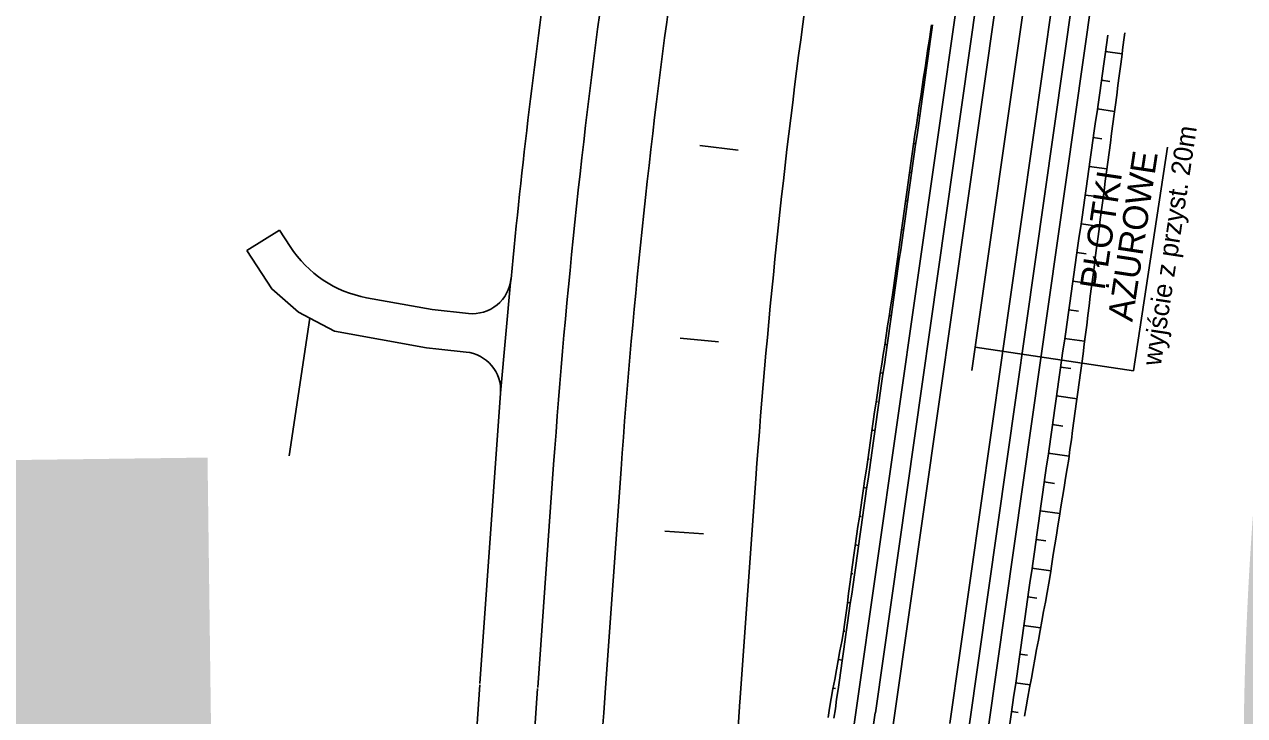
# Model space of a CAD drawing. Extents: x 6503541 to 6503743, y 5888004 to 5888145.
# Drawn here: x 6503702.276 to 6503703.793, y 5888115.915 to 5888116.773 of the extents above; entities that cross this region are included whole.
import ezdxf

# ---------------------------------------------------------------- set-up
doc = ezdxf.new("R2010")
doc.units = 0
doc.layers.add('12', color=7, linetype='Continuous')

msp = doc.modelspace()

# ---------------------------------------------------------------- linework, layer by layer
at = {"layer": '12'}
for p, q in [((6503703.334, 5888115.918), (6503705.1445, 5888128.6327)), ((6503703.3577, 5888115.9146), (6503705.1683, 5888128.6294)), ((6503703.4266, 5888115.9048), (6503705.2372, 5888128.6195)), ((6503703.4504, 5888115.9014), (6503705.2609, 5888128.6162)), ((6503703.3102, 5888115.9214), (6503703.44, 5888116.8329)), ((6503703.5216, 5888116.8185), (6503703.4539, 5888116.3433)), ((6503703.4741, 5888115.898), (6503703.6039, 5888116.8095)), ((6503703.4032, 5888116.7677), (6503703.4045, 5888116.7675)), ((6503703.6201, 5888116.7394), (6503703.6407, 5888116.7365)), ((6503703.3986, 5888116.732), (6503703.3978, 5888116.7321)), ((6503703.3923, 5888116.6965), (6503703.3944, 5888116.6962)), ((6503703.6255, 5888116.7023), (6503703.615, 5888116.7038)), ((6503703.3881, 5888116.6607), (6503703.3869, 5888116.6609)), ((6503703.61, 5888116.6681), (6503703.6313, 5888116.6651)), ((6503703.6157, 5888116.6309), (6503703.6049, 5888116.6325)), ((6503703.3815, 5888116.6253), (6503703.3842, 5888116.6249)), ((6503703.6971, 5888116.6205), (6503703.6547, 5888116.343)), ((6503703.3778, 5888116.5895), (6503703.3765, 5888116.5897)), ((6503703.5998, 5888116.5968), (6503703.6219, 5888116.5937)), ((6503703.3715, 5888116.554), (6503703.3741, 5888116.5537)), ((6503703.6059, 5888116.5596), (6503703.5947, 5888116.5612)), ((6503703.5897, 5888116.5256), (6503703.6124, 5888116.5223)), ((6503702.5936, 5888116.5175), (6503702.5529, 5888116.4921)), ((6503702.5936, 5888116.5175), (6503702.6068, 5888116.4971)), ((6503703.3678, 5888116.5182), (6503703.3665, 5888116.5184)), ((6503703.3616, 5888116.4827), (6503703.3639, 5888116.4824)), ((6503703.5962, 5888116.4883), (6503703.5846, 5888116.4899)), ((6503702.8682, 5888116.3149), (6503702.8811, 5888116.4572)), ((6503703.3577, 5888116.4469), (6503703.3566, 5888116.4471)), ((6503703.5795, 5888116.4543), (6503703.6032, 5888116.4509)), ((6503702.7831, 5888116.4188), (6503702.7017, 5888116.4337)), ((6503702.8284, 5888116.414), (6503702.7831, 5888116.4188)), ((6503703.5865, 5888116.4169), (6503703.5744, 5888116.4186)), ((6503702.6053, 5888116.2374), (6503702.6311, 5888116.4082)), ((6503703.3512, 5888116.4115), (6503703.3538, 5888116.4111)), ((6503703.3473, 5888116.3756), (6503703.3459, 5888116.3759)), ((6503703.6547, 5888116.343), (6503703.458, 5888116.3721)), ((6503703.5693, 5888116.383), (6503703.5941, 5888116.3795)), ((6503702.8253, 5888116.3661), (6503702.7915, 5888116.3696)), ((6503703.5769, 5888116.3456), (6503703.5643, 5888116.3474)), ((6503703.3403, 5888116.3403), (6503703.3436, 5888116.3398)), ((6503702.8682, 5888116.3149), (6503702.8425, 5888115.9544)), ((6503703.5592, 5888116.3117), (6503703.5847, 5888116.3081)), ((6503703.3368, 5888116.3044), (6503703.335, 5888116.3047)), ((6503703.3298, 5888116.2691), (6503703.3335, 5888116.2685)), ((6503703.5669, 5888116.2742), (6503703.5541, 5888116.2761)), ((6503703.549, 5888116.2404), (6503703.5748, 5888116.2368)), ((6503702.9341, 5888116.2266), (6503702.9143, 5888115.9493)), ((6503703.0179, 5888116.2206), (6503702.9981, 5888115.9433)), ((6503703.3265, 5888116.2332), (6503703.3247, 5888116.2334)), ((6503703.1855, 5888116.2087), (6503703.1657, 5888115.9314)), ((6503703.5565, 5888116.203), (6503703.544, 5888116.2048)), ((6503703.3195, 5888116.1978), (6503703.3233, 5888116.1972)), ((6503703.3163, 5888116.1619), (6503703.3143, 5888116.1622)), ((6503703.5389, 5888116.1691), (6503703.5634, 5888116.1657)), ((6503703.5457, 5888116.1318), (6503703.5338, 5888116.1335)), ((6503703.3092, 5888116.1265), (6503703.3132, 5888116.126)), ((6503703.5287, 5888116.0979), (6503703.5522, 5888116.0945)), ((6503703.3061, 5888116.0906), (6503703.3042, 5888116.0909)), ((6503703.2993, 5888116.0552), (6503703.303, 5888116.0547)), ((6503703.5348, 5888116.0606), (6503703.5237, 5888116.0622)), ((6503703.5186, 5888116.0266), (6503703.5394, 5888116.0236)), ((6503703.2962, 5888116.0193), (6503703.2945, 5888116.0196)), ((6503703.288, 5888115.9841), (6503703.2928, 5888115.9833)), ((6503703.5232, 5888115.9896), (6503703.5135, 5888115.9909)), ((6503703.2846, 5888115.9482), (6503703.2815, 5888115.9487)), ((6503703.5084, 5888115.9553), (6503703.5264, 5888115.9528)), ((6503703.5116, 5888115.9185), (6503703.5034, 5888115.9197))]:
    msp.add_line(p, q, dxfattribs=at)
for points in [[(6503703.2753, 5888115.9123), (6503703.2772, 5888115.924), (6503703.2791, 5888115.9359), (6503703.2813, 5888115.9477), (6503703.2835, 5888115.9595), (6503703.2856, 5888115.9713), (6503703.2878, 5888115.9831), (6503703.29, 5888115.9949), (6503703.2922, 5888116.0067), (6503703.2943, 5888116.0186), (6503703.2959, 5888116.0305), (6503703.2976, 5888116.0423), (6503703.2992, 5888116.0542), (6503703.3008, 5888116.0661), (6503703.3024, 5888116.078), (6503703.304, 5888116.0899), (6503703.3057, 5888116.1018), (6503703.3073, 5888116.1137), (6503703.309, 5888116.1256), (6503703.3107, 5888116.1374), (6503703.3124, 5888116.1493), (6503703.3142, 5888116.1612), (6503703.3159, 5888116.1731), (6503703.3176, 5888116.1849), (6503703.3193, 5888116.1968), (6503703.3211, 5888116.2087), (6503703.3228, 5888116.2206), (6503703.3245, 5888116.2324), (6503703.3262, 5888116.2443), (6503703.328, 5888116.2562), (6503703.3297, 5888116.2681), (6503703.3314, 5888116.2799), (6503703.3331, 5888116.2918), (6503703.3349, 5888116.3037), (6503703.3366, 5888116.3156), (6503703.3383, 5888116.3274), (6503703.3401, 5888116.3393), (6503703.342, 5888116.3512), (6503703.3439, 5888116.363), (6503703.3457, 5888116.3749), (6503703.3475, 5888116.3867), (6503703.3493, 5888116.3986), (6503703.3511, 5888116.4105), (6503703.3529, 5888116.4223), (6503703.3547, 5888116.4342), (6503703.3565, 5888116.4461), (6503703.3581, 5888116.458), (6503703.3598, 5888116.4698), (6503703.3614, 5888116.4817), (6503703.3631, 5888116.4936), (6503703.3647, 5888116.5055), (6503703.3664, 5888116.5174), (6503703.3681, 5888116.5293), (6503703.3697, 5888116.5412), (6503703.3714, 5888116.553), (6503703.373, 5888116.5649), (6503703.3747, 5888116.5768), (6503703.3763, 5888116.5887), (6503703.378, 5888116.6006), (6503703.3796, 5888116.6125), (6503703.3813, 5888116.6243), (6503703.3831, 5888116.6362), (6503703.385, 5888116.6481), (6503703.3868, 5888116.6599), (6503703.3886, 5888116.6718), (6503703.3904, 5888116.6837), (6503703.3922, 5888116.6955), (6503703.394, 5888116.7074), (6503703.3958, 5888116.7193), (6503703.3976, 5888116.7311), (6503703.3994, 5888116.743), (6503703.4012, 5888116.7548), (6503703.403, 5888116.7667), (6503703.4039, 5888116.7726)], [(6503703.2826, 5888115.9112), (6503703.2843, 5888115.923), (6503703.2859, 5888115.9349), (6503703.2876, 5888115.9468), (6503703.2893, 5888115.9587), (6503703.291, 5888115.9705), (6503703.2927, 5888115.9824), (6503703.2944, 5888115.9943), (6503703.2961, 5888116.0062), (6503703.2978, 5888116.0181), (6503703.2995, 5888116.0299), (6503703.3012, 5888116.0418), (6503703.3029, 5888116.0537), (6503703.3046, 5888116.0656), (6503703.3063, 5888116.0775), (6503703.3079, 5888116.0893), (6503703.3096, 5888116.1012), (6503703.3113, 5888116.1131), (6503703.313, 5888116.125), (6503703.3147, 5888116.1369), (6503703.3164, 5888116.1488), (6503703.3181, 5888116.1606), (6503703.3198, 5888116.1725), (6503703.3215, 5888116.1844), (6503703.3232, 5888116.1963), (6503703.3249, 5888116.2082), (6503703.3266, 5888116.22), (6503703.3282, 5888116.2319), (6503703.3299, 5888116.2438), (6503703.3316, 5888116.2557), (6503703.3333, 5888116.2676), (6503703.335, 5888116.2794), (6503703.3367, 5888116.2913), (6503703.3384, 5888116.3032), (6503703.3401, 5888116.3151), (6503703.3418, 5888116.327), (6503703.3435, 5888116.3388), (6503703.3452, 5888116.3507), (6503703.3469, 5888116.3626), (6503703.3485, 5888116.3745), (6503703.3502, 5888116.3864), (6503703.3519, 5888116.3982), (6503703.3536, 5888116.4101), (6503703.3553, 5888116.422), (6503703.357, 5888116.4339), (6503703.3587, 5888116.4458), (6503703.3604, 5888116.4576), (6503703.3621, 5888116.4695), (6503703.3638, 5888116.4814), (6503703.3655, 5888116.4933), (6503703.3672, 5888116.5052), (6503703.3688, 5888116.517), (6503703.3705, 5888116.5289), (6503703.3722, 5888116.5408), (6503703.3739, 5888116.5527), (6503703.3756, 5888116.5646), (6503703.3773, 5888116.5764), (6503703.379, 5888116.5883), (6503703.3807, 5888116.6002), (6503703.3824, 5888116.6121), (6503703.3841, 5888116.624), (6503703.3858, 5888116.6358), (6503703.3875, 5888116.6477), (6503703.3891, 5888116.6596), (6503703.3908, 5888116.6715), (6503703.3925, 5888116.6834), (6503703.3942, 5888116.6952), (6503703.3959, 5888116.7071), (6503703.3976, 5888116.719), (6503703.3993, 5888116.7309), (6503703.401, 5888116.7428), (6503703.4027, 5888116.7546), (6503703.4044, 5888116.7665), (6503703.4052, 5888116.7725)], [(6503703.5012, 5888115.9043), (6503703.5029, 5888115.9161), (6503703.5046, 5888115.928), (6503703.5063, 5888115.9399), (6503703.508, 5888115.9518), (6503703.5097, 5888115.9637), (6503703.5114, 5888115.9755), (6503703.5131, 5888115.9874), (6503703.5147, 5888115.9993), (6503703.5164, 5888116.0112), (6503703.5181, 5888116.0231), (6503703.5198, 5888116.0349), (6503703.5215, 5888116.0468), (6503703.5232, 5888116.0587), (6503703.5249, 5888116.0706), (6503703.5266, 5888116.0825), (6503703.5283, 5888116.0943), (6503703.53, 5888116.1062), (6503703.5317, 5888116.1181), (6503703.5334, 5888116.13), (6503703.535, 5888116.1419), (6503703.5367, 5888116.1537), (6503703.5384, 5888116.1656), (6503703.5401, 5888116.1775), (6503703.5418, 5888116.1894), (6503703.5435, 5888116.2013), (6503703.5452, 5888116.2131), (6503703.5469, 5888116.225), (6503703.5486, 5888116.2369), (6503703.5503, 5888116.2488), (6503703.552, 5888116.2607), (6503703.5537, 5888116.2725), (6503703.5553, 5888116.2844), (6503703.557, 5888116.2963), (6503703.5587, 5888116.3082), (6503703.5604, 5888116.3201), (6503703.5621, 5888116.3319), (6503703.5638, 5888116.3438), (6503703.5655, 5888116.3557), (6503703.5672, 5888116.3676), (6503703.5689, 5888116.3795), (6503703.5706, 5888116.3913), (6503703.5723, 5888116.4032), (6503703.574, 5888116.4151), (6503703.5756, 5888116.427), (6503703.5773, 5888116.4389), (6503703.579, 5888116.4507), (6503703.5807, 5888116.4626), (6503703.5824, 5888116.4745), (6503703.5841, 5888116.4864), (6503703.5858, 5888116.4983), (6503703.5875, 5888116.5101), (6503703.5892, 5888116.522), (6503703.5909, 5888116.5339), (6503703.5926, 5888116.5458), (6503703.5943, 5888116.5577), (6503703.5959, 5888116.5695), (6503703.5976, 5888116.5814), (6503703.5993, 5888116.5933), (6503703.601, 5888116.6052), (6503703.6027, 5888116.6171), (6503703.6044, 5888116.6289), (6503703.6061, 5888116.6408), (6503703.6078, 5888116.6527), (6503703.6095, 5888116.6646), (6503703.6112, 5888116.6765), (6503703.6129, 5888116.6883), (6503703.6146, 5888116.7002), (6503703.6162, 5888116.7121), (6503703.6179, 5888116.724), (6503703.6196, 5888116.7359), (6503703.6213, 5888116.7477), (6503703.623, 5888116.7596)], [(6503703.5192, 5888115.9138), (6503703.5214, 5888115.9256), (6503703.5236, 5888115.9374), (6503703.5257, 5888115.9492), (6503703.5279, 5888115.9611), (6503703.5301, 5888115.9729), (6503703.5323, 5888115.9847), (6503703.5344, 5888115.9965), (6503703.5366, 5888116.0083), (6503703.5388, 5888116.0201), (6503703.541, 5888116.0319), (6503703.5431, 5888116.0437), (6503703.5453, 5888116.0555), (6503703.5475, 5888116.0674), (6503703.5497, 5888116.0792), (6503703.5517, 5888116.091), (6503703.5534, 5888116.1029), (6503703.5551, 5888116.1148), (6503703.557, 5888116.1266), (6503703.559, 5888116.1385), (6503703.5609, 5888116.1503), (6503703.5628, 5888116.1621), (6503703.5647, 5888116.174), (6503703.5666, 5888116.1858), (6503703.5686, 5888116.1977), (6503703.5705, 5888116.2095), (6503703.5724, 5888116.2214), (6503703.5743, 5888116.2332), (6503703.5759, 5888116.2451), (6503703.5776, 5888116.257), (6503703.5792, 5888116.2689), (6503703.5809, 5888116.2808), (6503703.5825, 5888116.2927), (6503703.5842, 5888116.3046), (6503703.5858, 5888116.3164), (6503703.5875, 5888116.3283), (6503703.589, 5888116.3402), (6503703.5905, 5888116.3521), (6503703.5921, 5888116.364), (6503703.5936, 5888116.3759), (6503703.5951, 5888116.3878), (6503703.5967, 5888116.3997), (6503703.5982, 5888116.4117), (6503703.5997, 5888116.4236), (6503703.6012, 5888116.4355), (6503703.6028, 5888116.4474), (6503703.6043, 5888116.4593), (6503703.6058, 5888116.4712), (6503703.6074, 5888116.4831), (6503703.6089, 5888116.495), (6503703.6104, 5888116.5069), (6503703.612, 5888116.5188), (6503703.6135, 5888116.5307), (6503703.6151, 5888116.5426), (6503703.6167, 5888116.5545), (6503703.6182, 5888116.5664), (6503703.6198, 5888116.5783), (6503703.6214, 5888116.5902), (6503703.623, 5888116.6021), (6503703.6245, 5888116.614), (6503703.6261, 5888116.6259), (6503703.6277, 5888116.6378), (6503703.6293, 5888116.6496), (6503703.6308, 5888116.6615), (6503703.6324, 5888116.6734), (6503703.634, 5888116.6853), (6503703.6355, 5888116.6972), (6503703.6371, 5888116.7091), (6503703.6387, 5888116.721), (6503703.6403, 5888116.7329), (6503703.6418, 5888116.7448), (6503703.6434, 5888116.7567), (6503703.6442, 5888116.7627)], [(6503703.1636, 5888116.6171), (6503703.116, 5888116.6227)], [(6503702.5529, 5888116.4921), (6503702.5837, 5888116.4445), (6503702.617, 5888116.4155), (6503702.6311, 5888116.4082)], [(6503702.6311, 5888116.4082), (6503702.6617, 5888116.3922), (6503702.7762, 5888116.3712), (6503702.7915, 5888116.3696)], [(6503703.139, 5888116.379), (6503703.0912, 5888116.3833)], [(6503703.1204, 5888116.1402), (6503703.0725, 5888116.1436)]]:
    msp.add_lwpolyline(points, dxfattribs=at)
for centre, radius, start, end in [((6503712.0789, 5888115.5745), 9.24, 171.89568, 174.5184), ((6503712.0789, 5888115.5745), 9.168, 171.89568, 175.92139), ((6503712.0789, 5888115.5745), 9.084, 171.89568, 175.92139), ((6503712.0789, 5888115.5745), 8.916, 171.89568, 175.92139), ((6503702.7277, 5888116.5753), 0.144, 212.9015, 259.6029), ((6503702.8334, 5888116.4618), 0.048, 264.0345, 354.5184), ((6503702.8203, 5888116.3184), 0.048, 355.9214, 84.0345), ((6503697.0946, 5888116.3273), 5.76, 348.53445, 356.27387), ((6503697.0946, 5888116.3273), 5.832, 348.53445, 356.27387), ((6503697.0946, 5888116.3273), 5.916, 348.53445, 356.27387), ((6503697.0946, 5888116.3273), 6.084, 348.53445, 356.27387), ((6503685.5719, 5888118.4473), 17.9412, 322.48762, 351.89568), ((6503685.5719, 5888118.4473), 17.9172, 324.73339, 351.89568), ((6503685.5719, 5888118.4473), 17.9652, 322.48762, 351.89568)]:
    msp.add_arc(centre, radius, start, end, dxfattribs=at)

# ---------------------------------------------------------------- texts
for s, height, rotation, p in [('17', 4.22297, 0.7393, (6503699.6452, 5888115.7396)), ('wyjście z przyst. 20m', 0.023802, 81.3873, (6503703.6887, 5888116.3481)), ('AŻUROWE', 0.0311, 81.3873, (6503703.6534, 5888116.4029)), ('PŁOTKI', 0.0311, 81.3873, (6503703.6187, 5888116.4423))]:
    msp.add_text(s, height=height, rotation=rotation, dxfattribs=at).set_placement(p)

doc.saveas('drawing.dxf')
